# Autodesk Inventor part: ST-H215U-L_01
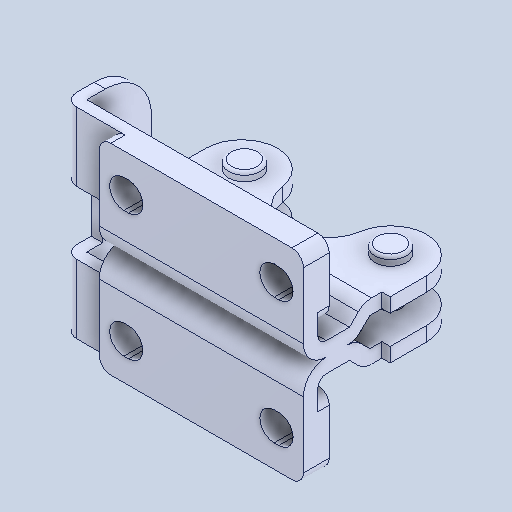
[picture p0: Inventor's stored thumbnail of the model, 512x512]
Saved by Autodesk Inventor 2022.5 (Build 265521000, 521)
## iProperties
Created: 2024-07
Part Number: ST-H215U-L_01
Material: 一般
Document SubType Name: Modeling
Designer: ImaoCorp
Density: 1 g/cm^3
Appearance: 既定
Author: ImaoCorp
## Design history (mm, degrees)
feature "ST-H215U-L_01"
node "ソリッド1"
